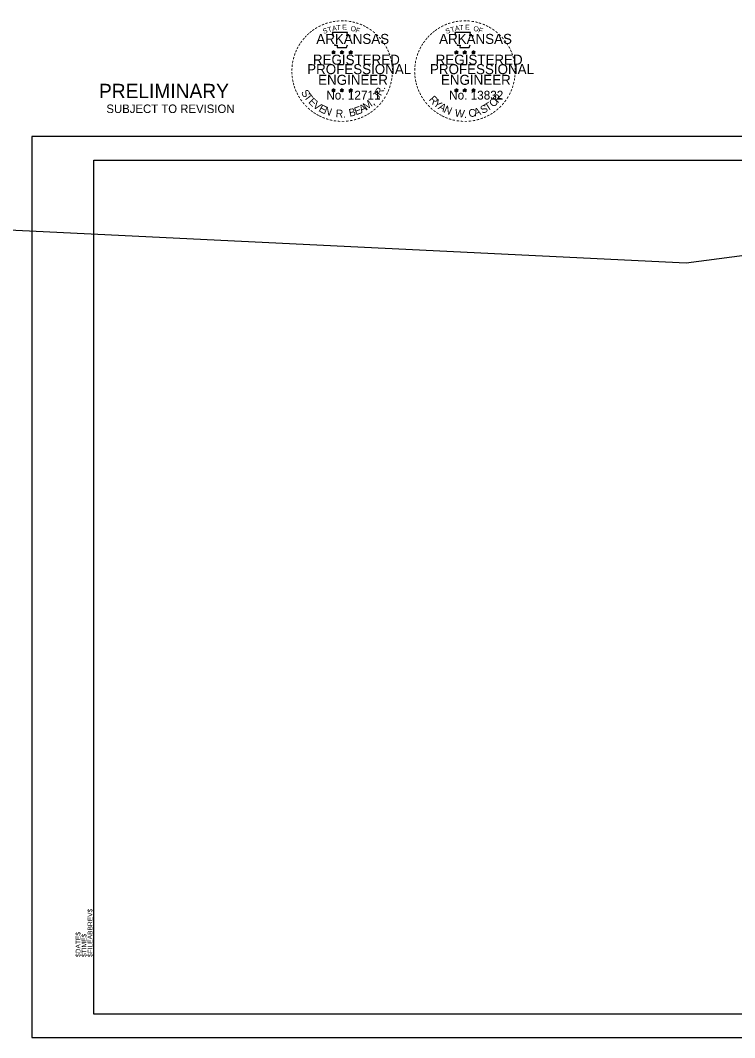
# Model space of a CAD drawing. Extents: x -12.3 to 43.6, y -0.6 to 24.3.
# Drawn here: x -1.8 to 15.65, y -0.58 to 24.26 of the extents above; entities that cross this region are included whole.
import ezdxf

# ---------------------------------------------------------------- set-up
doc = ezdxf.new("R2010")
doc.units = 0
doc.layers.add('PE_Stamp', color=7, linetype='Continuous')
doc.layers.add('R_Border', color=7, linetype='Continuous')

msp = doc.modelspace()

# ---------------------------------------------------------------- linework, layer by layer
at = {"layer": 'PE_Stamp'}
for p, q in [((5.814, 23.493), (5.856, 23.479)), ((5.814, 23.493), (5.845, 23.487)), ((5.814, 23.493), (5.843, 23.478)), ((5.83, 23.443), (5.856, 23.479)), ((5.83, 23.443), (5.846, 23.473)), ((5.83, 23.443), (5.856, 23.469)), ((5.856, 23.524), (5.851, 23.493)), ((5.856, 23.479), (5.856, 23.524)), ((5.856, 23.524), (5.862, 23.493)), ((5.899, 23.493), (5.856, 23.479)), ((5.882, 23.443), (5.856, 23.479)), ((5.882, 23.443), (5.856, 23.469)), ((5.899, 23.493), (5.864, 23.487)), ((5.882, 23.443), (5.866, 23.478)), ((5.899, 23.493), (5.874, 23.48)), ((6.018, 23.493), (6.06, 23.479)), ((6.018, 23.493), (6.049, 23.487)), ((6.018, 23.493), (6.047, 23.478)), ((6.034, 23.443), (6.06, 23.479)), ((6.034, 23.443), (6.049, 23.473)), ((6.034, 23.443), (6.06, 23.469)), ((6.06, 23.524), (6.055, 23.493)), ((6.06, 23.479), (6.06, 23.524)), ((6.06, 23.524), (6.066, 23.493)), ((6.103, 23.493), (6.06, 23.479)), ((6.086, 23.443), (6.06, 23.479)), ((6.086, 23.443), (6.06, 23.469)), ((6.103, 23.493), (6.068, 23.487)), ((6.086, 23.443), (6.07, 23.478)), ((6.103, 23.493), (6.078, 23.48)), ((6.233, 23.491), (6.276, 23.478)), ((6.233, 23.491), (6.264, 23.486)), ((6.233, 23.491), (6.262, 23.476)), ((6.249, 23.441), (6.276, 23.478)), ((6.249, 23.441), (6.265, 23.471)), ((6.249, 23.441), (6.275, 23.468)), ((6.276, 23.522), (6.271, 23.492)), ((6.302, 23.441), (6.275, 23.468)), ((6.276, 23.478), (6.276, 23.522)), ((6.276, 23.522), (6.282, 23.492)), ((6.318, 23.491), (6.276, 23.478)), ((6.302, 23.441), (6.276, 23.478)), ((6.318, 23.491), (6.283, 23.485)), ((6.302, 23.441), (6.285, 23.477)), ((6.318, 23.491), (6.293, 23.479)), ((8.814, 23.493), (8.856, 23.479)), ((8.814, 23.493), (8.845, 23.487)), ((8.814, 23.493), (8.843, 23.478)), ((8.83, 23.443), (8.856, 23.479)), ((8.83, 23.443), (8.846, 23.473)), ((8.83, 23.443), (8.856, 23.469)), ((8.856, 23.524), (8.851, 23.493)), ((8.856, 23.479), (8.856, 23.524)), ((8.856, 23.524), (8.862, 23.493)), ((8.899, 23.493), (8.856, 23.479)), ((8.882, 23.443), (8.856, 23.479)), ((8.882, 23.443), (8.856, 23.469)), ((8.899, 23.493), (8.864, 23.487)), ((8.882, 23.443), (8.866, 23.478)), ((8.899, 23.493), (8.874, 23.48)), ((9.018, 23.493), (9.06, 23.479)), ((9.018, 23.493), (9.049, 23.487)), ((9.018, 23.493), (9.047, 23.478)), ((9.034, 23.443), (9.06, 23.479)), ((9.034, 23.443), (9.049, 23.473)), ((9.034, 23.443), (9.06, 23.469)), ((9.06, 23.524), (9.055, 23.493)), ((9.06, 23.479), (9.06, 23.524)), ((9.06, 23.524), (9.066, 23.493)), ((9.103, 23.493), (9.06, 23.479)), ((9.086, 23.443), (9.06, 23.479)), ((9.086, 23.443), (9.06, 23.469)), ((9.103, 23.493), (9.068, 23.487)), ((9.086, 23.443), (9.07, 23.478)), ((9.103, 23.493), (9.078, 23.48)), ((9.233, 23.491), (9.276, 23.478)), ((9.233, 23.491), (9.264, 23.486)), ((9.233, 23.491), (9.262, 23.476)), ((9.249, 23.441), (9.276, 23.478)), ((9.249, 23.441), (9.265, 23.471)), ((9.249, 23.441), (9.275, 23.468)), ((9.276, 23.522), (9.271, 23.492)), ((9.302, 23.441), (9.275, 23.468)), ((9.276, 23.478), (9.276, 23.522)), ((9.276, 23.522), (9.282, 23.492)), ((9.318, 23.491), (9.276, 23.478)), ((9.302, 23.441), (9.276, 23.478)), ((9.318, 23.491), (9.283, 23.485)), ((9.302, 23.441), (9.285, 23.477)), ((9.318, 23.491), (9.293, 23.479)), ((5.813, 22.568), (5.856, 22.555)), ((5.813, 22.568), (5.844, 22.563)), ((5.813, 22.568), (5.842, 22.553)), ((5.83, 22.518), (5.856, 22.555)), ((5.83, 22.518), (5.845, 22.548)), ((5.83, 22.518), (5.856, 22.545)), ((5.856, 22.599), (5.851, 22.568)), ((5.856, 22.555), (5.856, 22.599)), ((5.856, 22.599), (5.862, 22.569)), ((5.898, 22.568), (5.856, 22.555)), ((5.882, 22.518), (5.856, 22.555)), ((5.882, 22.518), (5.856, 22.545)), ((5.898, 22.568), (5.863, 22.562)), ((5.882, 22.518), (5.865, 22.554)), ((5.898, 22.568), (5.873, 22.556)), ((6.017, 22.568), (6.06, 22.555)), ((6.017, 22.568), (6.048, 22.563)), ((6.017, 22.568), (6.046, 22.553)), ((6.033, 22.518), (6.06, 22.555)), ((6.033, 22.518), (6.049, 22.548)), ((6.033, 22.518), (6.06, 22.545)), ((6.06, 22.599), (6.055, 22.568)), ((6.06, 22.555), (6.06, 22.599)), ((6.06, 22.599), (6.066, 22.569)), ((6.102, 22.568), (6.06, 22.555)), ((6.086, 22.518), (6.06, 22.555)), ((6.086, 22.518), (6.06, 22.545)), ((6.102, 22.568), (6.067, 22.562)), ((6.086, 22.518), (6.069, 22.554)), ((6.102, 22.568), (6.077, 22.556)), ((6.233, 22.567), (6.275, 22.553)), ((6.233, 22.567), (6.264, 22.562)), ((6.233, 22.567), (6.262, 22.552)), ((6.249, 22.517), (6.275, 22.553)), ((6.249, 22.517), (6.264, 22.547)), ((6.249, 22.517), (6.275, 22.544)), ((6.275, 22.598), (6.27, 22.567)), ((6.275, 22.553), (6.275, 22.598)), ((6.275, 22.598), (6.281, 22.568)), ((6.318, 22.567), (6.275, 22.553)), ((6.301, 22.517), (6.275, 22.553)), ((6.301, 22.517), (6.275, 22.543)), ((6.318, 22.567), (6.283, 22.561)), ((6.301, 22.517), (6.285, 22.553)), ((6.318, 22.567), (6.293, 22.555)), ((8.813, 22.568), (8.856, 22.555)), ((8.813, 22.568), (8.844, 22.563)), ((8.813, 22.568), (8.842, 22.553)), ((8.83, 22.518), (8.856, 22.555)), ((8.83, 22.518), (8.845, 22.548)), ((8.83, 22.518), (8.856, 22.545)), ((8.856, 22.599), (8.851, 22.568)), ((8.856, 22.555), (8.856, 22.599)), ((8.856, 22.599), (8.862, 22.569)), ((8.898, 22.568), (8.856, 22.555)), ((8.882, 22.518), (8.856, 22.555)), ((8.882, 22.518), (8.856, 22.545)), ((8.898, 22.568), (8.863, 22.562)), ((8.882, 22.518), (8.865, 22.554)), ((8.898, 22.568), (8.873, 22.556)), ((9.017, 22.568), (9.06, 22.555)), ((9.017, 22.568), (9.048, 22.563)), ((9.017, 22.568), (9.046, 22.553)), ((9.033, 22.518), (9.06, 22.555)), ((9.033, 22.518), (9.049, 22.548)), ((9.033, 22.518), (9.06, 22.545)), ((9.06, 22.599), (9.055, 22.568)), ((9.06, 22.555), (9.06, 22.599)), ((9.06, 22.599), (9.066, 22.569)), ((9.102, 22.568), (9.06, 22.555)), ((9.086, 22.518), (9.06, 22.555)), ((9.086, 22.518), (9.06, 22.545)), ((9.102, 22.568), (9.067, 22.562)), ((9.086, 22.518), (9.069, 22.554)), ((9.102, 22.568), (9.077, 22.556)), ((9.233, 22.567), (9.275, 22.553)), ((9.233, 22.567), (9.264, 22.562)), ((9.233, 22.567), (9.262, 22.552)), ((9.249, 22.517), (9.275, 22.553)), ((9.249, 22.517), (9.264, 22.547)), ((9.249, 22.517), (9.275, 22.544)), ((9.275, 22.598), (9.27, 22.567)), ((9.275, 22.553), (9.275, 22.598)), ((9.275, 22.598), (9.281, 22.568)), ((9.318, 22.567), (9.275, 22.553)), ((9.301, 22.517), (9.275, 22.553)), ((9.301, 22.517), (9.275, 22.543)), ((9.318, 22.567), (9.283, 22.561)), ((9.301, 22.517), (9.285, 22.553)), ((9.318, 22.567), (9.293, 22.555))]:
    msp.add_line(p, q, dxfattribs=at)
for points in [[(5.819, 23.966), (5.852, 23.865)], [(6.248, 23.854), (6.265, 23.888), (6.181, 23.885), (6.199, 23.966), (5.819, 23.966)], [(8.819, 23.966), (8.852, 23.865)], [(9.248, 23.854), (9.265, 23.888), (9.181, 23.885), (9.199, 23.966), (8.819, 23.966)], [(5.879, 23.67), (5.879, 23.66), (5.948, 23.657), (5.941, 23.6), (6.169, 23.6), (6.194, 23.665)], [(8.879, 23.67), (8.879, 23.66), (8.948, 23.657), (8.941, 23.6), (9.169, 23.6), (9.194, 23.665)], [(5.856, 23.524), (5.882, 23.443), (5.814, 23.493), (5.899, 23.493), (5.83, 23.443), (5.856, 23.524)], [(6.06, 23.524), (6.086, 23.443), (6.018, 23.493), (6.103, 23.493), (6.034, 23.443), (6.06, 23.524)], [(6.276, 23.522), (6.302, 23.441), (6.233, 23.491), (6.318, 23.491), (6.249, 23.441), (6.276, 23.522)], [(8.856, 23.524), (8.882, 23.443), (8.814, 23.493), (8.899, 23.493), (8.83, 23.443), (8.856, 23.524)], [(9.06, 23.524), (9.086, 23.443), (9.018, 23.493), (9.103, 23.493), (9.034, 23.443), (9.06, 23.524)], [(9.276, 23.522), (9.302, 23.441), (9.233, 23.491), (9.318, 23.491), (9.249, 23.441), (9.276, 23.522)], [(5.856, 22.599), (5.882, 22.518), (5.813, 22.568), (5.898, 22.568), (5.83, 22.518), (5.856, 22.599)], [(6.06, 22.599), (6.086, 22.518), (6.017, 22.568), (6.102, 22.568), (6.033, 22.518), (6.06, 22.599)], [(6.275, 22.598), (6.301, 22.517), (6.233, 22.567), (6.318, 22.567), (6.249, 22.517), (6.275, 22.598)], [(8.856, 22.599), (8.882, 22.518), (8.813, 22.568), (8.898, 22.568), (8.83, 22.518), (8.856, 22.599)], [(9.06, 22.599), (9.086, 22.518), (9.017, 22.568), (9.102, 22.568), (9.033, 22.518), (9.06, 22.599)], [(9.275, 22.598), (9.301, 22.517), (9.233, 22.567), (9.318, 22.567), (9.249, 22.517), (9.275, 22.598)]]:
    msp.add_lwpolyline(points, dxfattribs=at)
for centre, radius in [((5.856, 23.479), 0.021), ((5.856, 23.479), 0.0176), ((5.856, 23.479), 0.0141), ((5.856, 23.479), 0.0121), ((5.856, 23.479), 0.00912), ((5.856, 23.479), 0.00605), ((5.856, 23.479), 0.00362), ((6.06, 23.479), 0.021), ((6.06, 23.479), 0.0176), ((6.06, 23.479), 0.0141), ((6.06, 23.479), 0.0121), ((6.06, 23.479), 0.00912), ((6.06, 23.479), 0.00605), ((6.06, 23.479), 0.00362), ((6.276, 23.478), 0.021), ((6.276, 23.478), 0.0176), ((6.276, 23.478), 0.0141), ((6.276, 23.478), 0.0121), ((6.276, 23.478), 0.00912), ((6.276, 23.478), 0.00605), ((6.276, 23.478), 0.00362), ((8.856, 23.479), 0.021), ((8.856, 23.479), 0.0176), ((8.856, 23.479), 0.0141), ((8.856, 23.479), 0.0121), ((8.856, 23.479), 0.00912), ((8.856, 23.479), 0.00605), ((8.856, 23.479), 0.00362), ((9.06, 23.479), 0.021), ((9.06, 23.479), 0.0176), ((9.06, 23.479), 0.0141), ((9.06, 23.479), 0.0121), ((9.06, 23.479), 0.00912), ((9.06, 23.479), 0.00605), ((9.06, 23.479), 0.00362), ((9.276, 23.478), 0.021), ((9.276, 23.478), 0.0176), ((9.276, 23.478), 0.0141), ((9.276, 23.478), 0.0121), ((9.276, 23.478), 0.00912), ((9.276, 23.478), 0.00605), ((9.276, 23.478), 0.00362), ((5.856, 22.555), 0.021), ((5.856, 22.555), 0.0176), ((5.856, 22.555), 0.0141), ((5.856, 22.555), 0.0121), ((5.856, 22.555), 0.00912), ((5.856, 22.555), 0.00605), ((5.856, 22.555), 0.00362), ((6.06, 22.555), 0.021), ((6.06, 22.555), 0.0176), ((6.06, 22.555), 0.0141), ((6.06, 22.555), 0.0121), ((6.06, 22.555), 0.00912), ((6.06, 22.555), 0.00605), ((6.06, 22.555), 0.00362), ((6.275, 22.553), 0.021), ((6.275, 22.553), 0.0176), ((6.275, 22.553), 0.0141), ((6.275, 22.553), 0.0121), ((6.275, 22.553), 0.00912), ((6.275, 22.553), 0.00605), ((6.275, 22.553), 0.00362), ((8.856, 22.555), 0.021), ((8.856, 22.555), 0.0176), ((8.856, 22.555), 0.0141), ((8.856, 22.555), 0.0121), ((8.856, 22.555), 0.00912), ((8.856, 22.555), 0.00605), ((8.856, 22.555), 0.00362), ((9.06, 22.555), 0.021), ((9.06, 22.555), 0.0176), ((9.06, 22.555), 0.0141), ((9.06, 22.555), 0.0121), ((9.06, 22.555), 0.00912), ((9.06, 22.555), 0.00605), ((9.06, 22.555), 0.00362), ((9.275, 22.553), 0.021), ((9.275, 22.553), 0.0176), ((9.275, 22.553), 0.0141), ((9.275, 22.553), 0.0121), ((9.275, 22.553), 0.00912), ((9.275, 22.553), 0.00605), ((9.275, 22.553), 0.00362)]:
    msp.add_circle(centre, radius, dxfattribs=at)
at = {"layer": 'R_Border'}
for p, q in [((0, 20.846), (31.907, 20.846)), ((0, 0), (0, 20.846)), ((0.289, 20.846), (26.611, 20.846)), ((31.907, 0), (0, 0))]:
    msp.add_line(p, q, dxfattribs=at)
msp.add_lwpolyline([(32.484, 21.423), (-1.516, 21.423), (-1.516, -0.577), (32.484, -0.577)], close=True, dxfattribs=at)
msp.add_lwpolyline([(22.965, 19.451), (14.467, 18.334), (-11.105, 19.577)], dxfattribs=at)

# ---------------------------------------------------------------- texts
at = {"layer": 'PE_Stamp'}
for s, height, rotation, p in [('-', 0.195, 34.0636, (5.438, 23.987)), ('-', 0.195, 28.7918, (5.511, 24.032)), ('-', 0.195, 24.3072, (5.589, 24.071)), ('-', 0.195, 19.1761, (5.666, 24.104)), ('T', 0.122, 16.4036, (5.73, 23.967)), ('-', 0.195, 13.6302, (5.758, 24.133)), ('A', 0.122, 11.2132, (5.83, 23.998)), ('-', 0.195, 10.2193, (5.84, 24.153)), ('T', 0.122, 6.0228, (5.934, 24.018)), ('-', 0.195, 5.8968, (5.929, 24.166)), ('-', 0.195, 0.1862, (6.024, 24.175)), ('E', 0.122, 0.8323, (6.069, 24.032)), ('-', 0.195, 357.743, (6.112, 24.174)), ('-', 0.195, 352.1617, (6.203, 24.167)), ('O', 0.122, 350.4515, (6.265, 24.006)), ('-', 0.195, 347.2049, (6.29, 24.153)), ('-', 0.195, 342.3362, (6.368, 24.134)), ('-', 0.195, 337.8551, (6.458, 24.107)), ('-', 0.195, 334.1211, (6.535, 24.074)), ('-', 0.195, 329.6409, (6.605, 24.039)), ('-', 0.195, 34.0636, (8.438, 23.987)), ('-', 0.195, 28.7918, (8.511, 24.032)), ('-', 0.195, 24.3072, (8.589, 24.071)), ('-', 0.195, 19.1761, (8.666, 24.104)), ('T', 0.122, 16.4036, (8.73, 23.967)), ('-', 0.195, 13.6302, (8.758, 24.133)), ('A', 0.122, 11.2132, (8.83, 23.998)), ('-', 0.195, 10.2193, (8.84, 24.153)), ('T', 0.122, 6.0228, (8.934, 24.018)), ('-', 0.195, 5.8968, (8.929, 24.166)), ('-', 0.195, 0.1862, (9.024, 24.175)), ('E', 0.122, 0.8323, (9.069, 24.032)), ('-', 0.195, 357.743, (9.112, 24.174)), ('-', 0.195, 352.1617, (9.203, 24.167)), ('O', 0.122, 350.4515, (9.265, 24.006)), ('-', 0.195, 347.2049, (9.29, 24.153)), ('-', 0.195, 342.3362, (9.368, 24.134)), ('-', 0.195, 337.8551, (9.458, 24.107)), ('-', 0.195, 334.1211, (9.535, 24.074)), ('-', 0.195, 329.6409, (9.605, 24.039)), ('-', 0.195, 48.4231, (5.202, 23.783)), ('-', 0.195, 42.9622, (5.257, 23.842)), ('-', 0.195, 38.9507, (5.31, 23.893)), ('-', 0.195, 36.2317, (5.368, 23.939)), ('S', 0.122, 21.594, (5.618, 23.927)), ('F', 0.122, 340.0707, (6.381, 23.978)), ('-', 0.195, 325.8627, (6.684, 23.995)), ('-', 0.195, 320.5297, (6.758, 23.943)), ('-', 0.195, 315.5786, (6.832, 23.883)), ('-', 0.195, 309.8797, (6.901, 23.816)), ('-', 0.195, 48.4231, (8.202, 23.783)), ('-', 0.195, 42.9622, (8.257, 23.842)), ('-', 0.195, 38.9507, (8.31, 23.893)), ('-', 0.195, 36.2317, (8.368, 23.939)), ('S', 0.122, 21.594, (8.618, 23.927)), ('F', 0.122, 340.0707, (9.381, 23.978)), ('-', 0.195, 325.8627, (9.684, 23.995)), ('-', 0.195, 320.5297, (9.758, 23.943)), ('-', 0.195, 315.5786, (9.832, 23.883)), ('-', 0.195, 309.8797, (9.901, 23.816)), ('-', 0.195, 62.8713, (5.025, 23.516)), ('-', 0.195, 58.0706, (5.063, 23.591)), ('-', 0.195, 54.2325, (5.103, 23.655)), ('-', 0.195, 50.6142, (5.153, 23.724)), ('-', 0.195, 306.6522, (6.965, 23.743)), ('-', 0.171, 303.6753, (7.024, 23.673)), ('-', 0.195, 299.6684, (7.063, 23.599)), ('-', 0.195, 62.8713, (8.025, 23.516)), ('-', 0.195, 58.0706, (8.063, 23.591)), ('-', 0.195, 54.2325, (8.103, 23.655)), ('-', 0.195, 50.6142, (8.153, 23.724)), ('-', 0.195, 306.6522, (9.965, 23.743)), ('-', 0.171, 303.6753, (10.024, 23.673)), ('-', 0.195, 299.6684, (10.063, 23.599)), ('-', 0.195, 75.461, (4.942, 23.277)), ('-', 0.195, 72.3945, (4.966, 23.364)), ('-', 0.195, 67.7743, (4.993, 23.441)), ('-', 0.195, 294.6628, (7.103, 23.525)), ('-', 0.195, 290.5728, (7.134, 23.454)), ('-', 0.195, 285.1233, (7.163, 23.383)), ('-', 0.195, 75.461, (7.942, 23.277)), ('-', 0.195, 72.3945, (7.966, 23.364)), ('-', 0.195, 67.7743, (7.993, 23.441)), ('-', 0.195, 294.6628, (10.103, 23.525)), ('-', 0.195, 290.5728, (10.134, 23.454)), ('-', 0.195, 285.1233, (10.163, 23.383)), ('-', 0.195, 85.1863, (4.917, 23.106)), ('-', 0.195, 81.2013, (4.926, 23.19)), ('-', 0.195, 280.5493, (7.187, 23.293)), ('-', 0.195, 276.5962, (7.207, 23.199)), ('-', 0.195, 274.3301, (7.214, 23.111)), ('-', 0.195, 85.1863, (7.917, 23.106)), ('-', 0.195, 81.2013, (7.926, 23.19)), ('-', 0.195, 280.5493, (10.187, 23.293)), ('-', 0.195, 276.5962, (10.207, 23.199)), ('-', 0.195, 274.3301, (10.214, 23.111)), ('-', 0.195, 94.1959, (4.918, 22.931)), ('-', 0.195, 89.0622, (4.914, 23.02)), ('-', 0.195, 98.9479, (4.927, 22.85)), ('-', 0.195, 263.5172, (7.216, 22.952)), ('-', 0.195, 269.9407, (7.219, 23.034)), ('-', 0.195, 94.1959, (7.918, 22.931)), ('-', 0.195, 89.0622, (7.914, 23.02)), ('-', 0.195, 98.9479, (7.927, 22.85)), ('-', 0.195, 263.5172, (10.216, 22.952)), ('-', 0.195, 269.9407, (10.219, 23.034)), ('-', 0.195, 101.7149, (4.943, 22.761)), ('-', 0.195, 105.4578, (4.963, 22.688)), ('-', 0.195, 109.0874, (4.989, 22.611)), ('R.', 0.188, 60.8264, (7.011, 22.403)), ('-', 0.195, 252.8681, (7.172, 22.702)), ('-', 0.195, 255.7626, (7.194, 22.79)), ('-', 0.195, 260.9953, (7.208, 22.873)), ('-', 0.195, 101.7149, (7.943, 22.761)), ('-', 0.195, 105.4578, (7.963, 22.688)), ('-', 0.195, 109.0874, (7.989, 22.611)), ('-', 0.195, 252.8681, (10.172, 22.702)), ('-', 0.195, 255.7626, (10.194, 22.79)), ('-', 0.195, 260.9953, (10.208, 22.873)), ('-', 0.195, 114.0643, (5.02, 22.538)), ('-', 0.195, 115.7289, (5.058, 22.463)), ('-', 0.195, 120.4471, (5.101, 22.391)), ('S', 0.188, 299.1736, (5.055, 22.505)), ('T', 0.188, 307.2838, (5.125, 22.386)), ('E', 0.188, 315.394, (5.229, 22.255)), ('J', 0.188, 52.7162, (6.938, 22.308)), ('-', 0.195, 239.0712, (7.065, 22.451)), ('-', 0.195, 244.6197, (7.113, 22.543)), ('-', 0.195, 247.8887, (7.145, 22.62)), ('-', 0.195, 114.0643, (8.02, 22.538)), ('-', 0.195, 115.7289, (8.058, 22.463)), ('-', 0.195, 120.4471, (8.101, 22.391)), ('R', 0.188, 311.3389, (8.172, 22.321)), ('O', 0.188, 40.5509, (9.754, 22.127)), ('R', 0.188, 48.6611, (9.87, 22.23)), ('-', 0.195, 239.0712, (10.065, 22.451)), ('-', 0.195, 244.6197, (10.113, 22.543)), ('-', 0.195, 247.8887, (10.145, 22.62)), ('-', 0.195, 125.8934, (5.15, 22.323)), ('-', 0.195, 130.7181, (5.207, 22.255)), ('-', 0.195, 134.2238, (5.27, 22.189)), ('-', 0.195, 138.9338, (5.334, 22.132)), ('V', 0.188, 323.5042, (5.336, 22.152)), ('E', 0.188, 331.6144, (5.477, 22.053)), ('N', 0.188, 339.7245, (5.605, 21.986)), ('B', 0.188, 12.1653, (6.251, 21.907)), ('E', 0.188, 20.2755, (6.403, 21.943)), ('A', 0.188, 28.3856, (6.538, 21.995)), ('M,', 0.188, 36.4958, (6.658, 22.058)), ('-', 0.195, 221.0851, (6.841, 22.171)), ('-', 0.195, 225.7653, (6.905, 22.234)), ('-', 0.195, 231.2538, (6.963, 22.302)), ('-', 0.195, 233.8452, (7.016, 22.371)), ('-', 0.195, 125.8934, (8.15, 22.323)), ('-', 0.195, 130.7181, (8.207, 22.255)), ('-', 0.195, 134.2238, (8.27, 22.189)), ('-', 0.195, 138.9338, (8.334, 22.132)), ('Y', 0.188, 319.4491, (8.279, 22.204)), ('A', 0.188, 327.5593, (8.396, 22.106)), ('N', 0.188, 335.6695, (8.532, 22.021)), ('A', 0.188, 16.2204, (9.31, 21.917)), ('S', 0.188, 24.3305, (9.492, 21.976)), ('T', 0.188, 32.4407, (9.617, 22.036)), ('-', 0.195, 221.0851, (9.841, 22.171)), ('-', 0.195, 225.7653, (9.905, 22.234)), ('-', 0.195, 231.2538, (9.963, 22.302)), ('-', 0.195, 233.8452, (10.016, 22.371)), ('-', 0.195, 144.6463, (5.402, 22.082)), ('-', 0.195, 148.0898, (5.47, 22.037)), ('-', 0.195, 151.5704, (5.541, 21.998)), ('-', 0.195, 154.6002, (5.605, 21.967)), ('-', 0.195, 158.5612, (5.681, 21.936)), ('-', 0.195, 162.7983, (5.765, 21.91)), ('R.', 0.188, 355.9449, (5.903, 21.9)), ('-', 0.195, 200.7184, (6.489, 21.952)), ('-', 0.195, 204.2516, (6.564, 21.985)), ('-', 0.195, 207.3568, (6.641, 22.024)), ('-', 0.195, 212.2491, (6.709, 22.066)), ('-', 0.195, 215.7363, (6.774, 22.114)), ('-', 0.195, 144.6463, (8.402, 22.082)), ('-', 0.195, 148.0898, (8.47, 22.037)), ('-', 0.195, 151.5704, (8.541, 21.998)), ('-', 0.195, 154.6002, (8.605, 21.967)), ('-', 0.195, 158.5612, (8.681, 21.936)), ('-', 0.195, 162.7983, (8.765, 21.91)), ('W.', 0.188, 351.8898, (8.809, 21.916)), ('C', 0.188, 8.1102, (9.166, 21.895)), ('-', 0.195, 200.7184, (9.489, 21.952)), ('-', 0.195, 204.2516, (9.564, 21.985)), ('-', 0.195, 207.3568, (9.641, 22.024)), ('-', 0.195, 212.2491, (9.709, 22.066)), ('-', 0.195, 215.7363, (9.774, 22.114)), ('-', 0.195, 167.5555, (5.852, 21.89)), ('-', 0.195, 173.1155, (5.946, 21.877)), ('-', 0.195, 176.5183, (6.038, 21.87)), ('-', 0.195, 181.5918, (6.129, 21.873)), ('-', 0.195, 185.8167, (6.227, 21.882)), ('-', 0.195, 191.2858, (6.317, 21.898)), ('-', 0.195, 195.4743, (6.406, 21.922)), ('-', 0.195, 167.5555, (8.852, 21.89)), ('-', 0.195, 173.1155, (8.946, 21.877)), ('-', 0.195, 176.5183, (9.038, 21.87)), ('-', 0.195, 181.5918, (9.129, 21.873)), ('-', 0.195, 185.8167, (9.227, 21.882)), ('-', 0.195, 191.2858, (9.317, 21.898)), ('-', 0.195, 195.4743, (9.406, 21.922))]:
    msp.add_text(s, height=height, rotation=rotation, dxfattribs=at).set_placement(p)
for s, height, p in [('ARKANSAS', 0.2442, (5.435, 23.687)), ('ARKANSAS', 0.2442, (8.435, 23.687)), ('REGISTERED', 0.2442, (5.352, 23.18)), ('REGISTERED', 0.2442, (8.352, 23.18)), ('PROFESSIONAL', 0.24416, (5.212, 22.948)), ('PROFESSIONAL', 0.24416, (8.212, 22.948)), ('ENGINEER', 0.2442, (5.479, 22.688)), ('ENGINEER', 0.2442, (8.479, 22.688)), ('PRELIMINARY', 0.35, (0.126, 22.362)), ('No. 12711', 0.2145, (5.679, 22.328)), ('No. 13832', 0.2145, (8.679, 22.328)), ('SUBJECT TO REVISION', 0.20751, (0.307, 21.999))]:
    msp.add_text(s, height=height, dxfattribs=at).set_placement(p)
at = {"layer": 'R_Border'}
for s, height, p in [('$FILEABBREV$', 0.11723, (-0.034, 1.392)), ('$DATE$', 0.1172, (-0.327, 1.392)), ('$TIME$', 0.1172, (-0.18, 1.392))]:
    msp.add_text(s, height=height, rotation=90, dxfattribs=at).set_placement(p)

doc.saveas('drawing.dxf')
